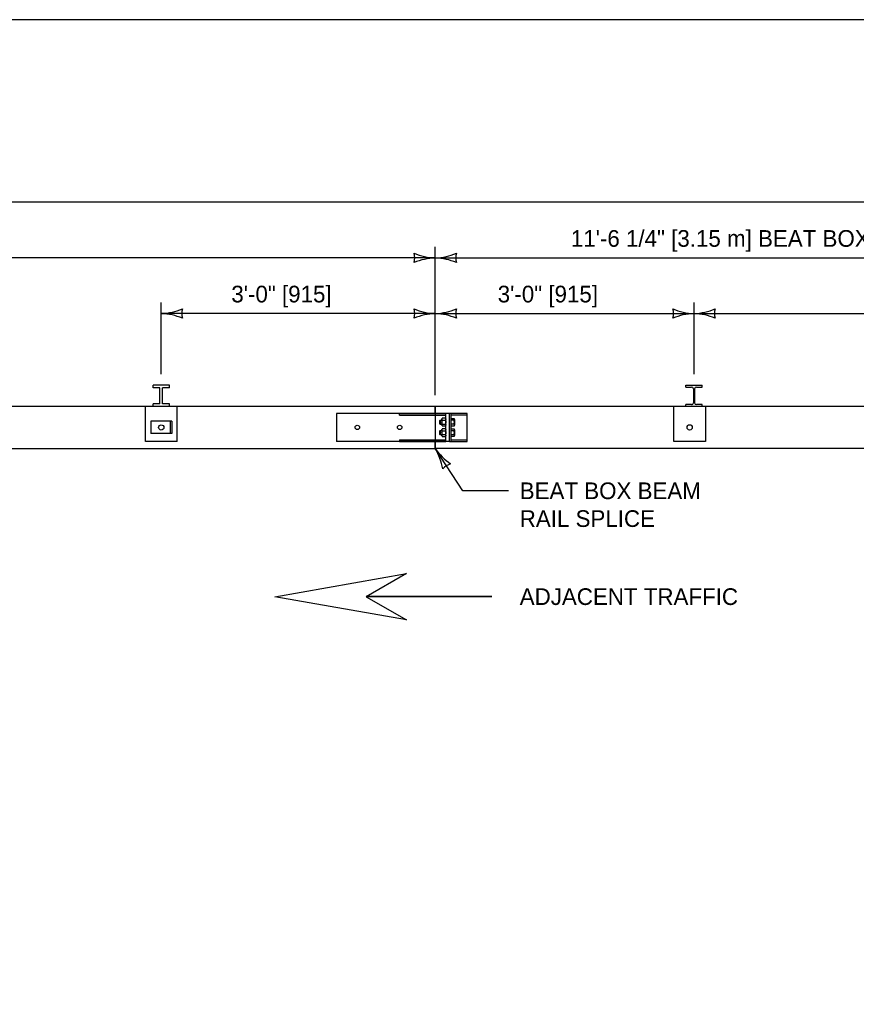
# Model space of a CAD drawing. Extents: x 49991.4 to 50021, y 49987.6 to 50011.4.
# Drawn here: x 50010.735 to 50013.742, y 49995.487 to 49998.999 of the extents above; entities that cross this region are included whole.
import ezdxf

# ---------------------------------------------------------------- set-up
doc = ezdxf.new("R2010")
doc.units = 0
for name, color, linetype in [('Level 1', 7, 'Continuous'), ('Level 2', 7, 'Continuous'), ('Level 3', 7, 'Continuous'), ('Level 4', 7, 'Continuous'), ('Level 63', 7, 'Continuous')]:
    doc.layers.add(name, color=color, linetype=linetype)

# ---------------------------------------------------------------- blocks, each defined once
blk = doc.blocks.new('HEX$NU')
at = {"layer": 'Level 63'}
for p, q in [((0, -0.32), (0, 0.32)), ((0.03, 0.43), (0.42, 0.43)), ((0.03, 0.22), (0.42, 0.22)), ((0.45, 0.32), (0.45, -0.32)), ((0.03, -0.22), (0.42, -0.22)), ((0.42, -0.43), (0.03, -0.43))]:
    blk.add_line(p, q, dxfattribs=at)
for centre, radius, start, end in [((0.21, 0.32), 0.21, 149.0201, 210.9799), ((0.8, 0), 0.796, 164.2217, 195.7782), ((0.24, 0.32), 0.21, 329.0201, 30.9799), ((-0.35, 0), 0.796, 344.2218, 15.7783), ((0.21, -0.32), 0.21, 149.0201, 210.9799), ((0.24, -0.32), 0.21, 329.0201, 30.9799)]:
    blk.add_arc(centre, radius, start, end, dxfattribs=at)

msp = doc.modelspace()

# ---------------------------------------------------------------- linework, layer by layer
at = {"layer": 'Level 1'}
for p, q in [((50011.2143, 49997.6755), (50011.2143, 49997.6847)), ((50011.2734, 49997.6847), (50011.2143, 49997.6847)), ((50011.2393, 49997.6755), (50011.2143, 49997.6755)), ((50011.2393, 49997.6179), (50011.2393, 49997.6755)), ((50011.2484, 49997.6179), (50011.2484, 49997.6755)), ((50011.2734, 49997.6755), (50011.2484, 49997.6755)), ((50011.2734, 49997.6755), (50011.2734, 49997.6847)), ((50013.1289, 49997.6846), (50013.1881, 49997.6846)), ((50013.1289, 49997.678), (50013.1289, 49997.6846)), ((50013.1289, 49997.678), (50013.15, 49997.678)), ((50013.1563, 49997.6717), (50013.1563, 49997.6216)), ((50013.1607, 49997.6717), (50013.1607, 49997.6216)), ((50013.167, 49997.678), (50013.1881, 49997.678)), ((50013.1881, 49997.678), (50013.1881, 49997.6846)), ((50012.2286, 49997.6087), (50006.713, 49997.6087)), ((50011.2393, 49997.6179), (50011.2143, 49997.6179)), ((50011.2143, 49997.6087), (50011.2143, 49997.6179)), ((50011.2734, 49997.6179), (50011.2484, 49997.6179)), ((50011.2734, 49997.6087), (50011.2734, 49997.6179)), ((50015.8846, 49997.6087), (50012.2286, 49997.6087)), ((50012.2286, 49997.5834), (50012.2286, 49997.6087)), ((50012.2286, 49997.6087), (50012.2286, 49997.5834)), ((50013.1998, 49997.6087), (50013.0855, 49997.6087)), ((50013.1289, 49997.6087), (50013.1289, 49997.6153)), ((50013.15, 49997.6153), (50013.1289, 49997.6153)), ((50013.1881, 49997.6087), (50013.1289, 49997.6087)), ((50013.1881, 49997.6153), (50013.167, 49997.6153)), ((50013.1881, 49997.6087), (50013.1881, 49997.6153)), ((50011.8732, 49997.5834), (50011.8732, 49997.4821)), ((50012.2794, 49997.5834), (50011.8732, 49997.5834)), ((50012.1001, 49997.5834), (50012.2667, 49997.5834)), ((50012.1001, 49997.577), (50012.1001, 49997.5834)), ((50012.1001, 49997.577), (50012.2667, 49997.577)), ((50012.2286, 49997.5834), (50012.2286, 49997.4821)), ((50012.2286, 49997.5834), (50012.2286, 49997.4821)), ((50012.2667, 49997.4821), (50012.2667, 49997.5834)), ((50012.2794, 49997.4821), (50012.2794, 49997.5834)), ((50012.2794, 49997.4821), (50012.2794, 49997.5834)), ((50012.3429, 49997.5834), (50012.2794, 49997.5834)), ((50012.2858, 49997.4821), (50012.2858, 49997.5834)), ((50012.3429, 49997.577), (50012.2858, 49997.577)), ((50012.3429, 49997.4821), (50012.3429, 49997.5834)), ((50011.206, 49997.555), (50011.206, 49997.5106)), ((50011.282, 49997.555), (50011.206, 49997.555)), ((50011.2756, 49997.555), (50011.2756, 49997.5106)), ((50011.282, 49997.555), (50011.282, 49997.5106)), ((50012.2461, 49997.5596), (50012.2445, 49997.558)), ((50012.2445, 49997.5454), (50012.2445, 49997.558)), ((50012.2461, 49997.5438), (50012.2445, 49997.5454)), ((50012.2461, 49997.5596), (50012.2461, 49997.5438)), ((50012.2461, 49997.5596), (50012.2525, 49997.5596)), ((50012.2525, 49997.558), (50012.2461, 49997.558)), ((50012.2461, 49997.5454), (50012.2525, 49997.5454)), ((50012.2525, 49997.5438), (50012.2461, 49997.5438)), ((50012.2962, 49997.5586), (50012.2858, 49997.5586)), ((50012.2962, 49997.5449), (50012.2858, 49997.5449)), ((50012.2973, 49997.562), (50012.2973, 49997.5414)), ((50011.282, 49997.5106), (50011.206, 49997.5106)), ((50012.2461, 49997.5217), (50012.2445, 49997.5201)), ((50012.2445, 49997.5074), (50012.2445, 49997.5201)), ((50012.2461, 49997.5058), (50012.2445, 49997.5074)), ((50012.2461, 49997.5217), (50012.2461, 49997.5058)), ((50012.2461, 49997.5217), (50012.2525, 49997.5217)), ((50012.2525, 49997.5201), (50012.2461, 49997.5201)), ((50012.2461, 49997.5074), (50012.2525, 49997.5074)), ((50012.2525, 49997.5058), (50012.2461, 49997.5058)), ((50012.2962, 49997.5206), (50012.2858, 49997.5206)), ((50012.2962, 49997.5069), (50012.2858, 49997.5069)), ((50012.2973, 49997.524), (50012.2973, 49997.5035)), ((50012.2794, 49997.4821), (50011.8732, 49997.4821)), ((50012.1001, 49997.4884), (50012.1001, 49997.4821)), ((50012.1001, 49997.4884), (50012.2667, 49997.4884)), ((50012.1001, 49997.4821), (50012.2667, 49997.4821)), ((50012.2286, 49997.4821), (50012.2286, 49997.4568)), ((50012.2286, 49997.4568), (50012.2286, 49997.4821)), ((50012.2794, 49997.4821), (50012.3429, 49997.4821)), ((50012.2858, 49997.4884), (50012.3429, 49997.4884)), ((50015.8846, 49997.4568), (50012.2286, 49997.4568)), ((50012.2286, 49997.4568), (50012.2286, 49997.4568)), ((50012.4322, 49996.9249), (50011.9803, 49996.9249)), ((50012.4322, 49996.9244), (50011.9803, 49996.9244))]:
    msp.add_line(p, q, dxfattribs=at)
for points in [[(49999.3835, 49998.9992), (50016.7501, 49998.9992), (50016.7501, 49987.7988), (49999.3835, 49987.7988)], [(50012.1248, 49996.8411), (50011.6519, 49996.9244), (50012.1248, 49997.0082), (50011.9805, 49996.9244)]]:
    msp.add_lwpolyline(points, close=True, dxfattribs=at)
for points in [[(50012.2962, 49997.538), (50012.2858, 49997.538), (50012.2858, 49997.5654), (50012.2962, 49997.5654)], [(50012.2962, 49997.5), (50012.2858, 49997.5), (50012.2858, 49997.5274), (50012.2962, 49997.5274)], [(50006.713, 49997.4568), (50012.2286, 49997.4568)]]:
    msp.add_lwpolyline(points, dxfattribs=at)
for centre in [(50011.244, 49997.5328), (50013.1429, 49997.5331)]:
    msp.add_circle(centre, 0.00948, dxfattribs=at)
for centre, major_axis, start_param, end_param in [((50013.15, 49997.6717), (-0.00635, 0), 3.141593, 4.712389), ((50013.167, 49997.6717), (-0.00635, 0), 4.712389, 6.283185), ((50013.15, 49997.6216), (-0.00635, 0), 1.570796, 3.141593), ((50013.167, 49997.6216), (-0.00635, 0), 0, 1.570796), ((50012.2914, 49997.562), (-0.00587, 0), 2.516161, 3.767024), ((50012.2755, 49997.5517), (-0.0218, 0), 2.821042, 3.462143), ((50012.2914, 49997.5414), (-0.00587, 0), 2.516163, 3.767023), ((50012.2914, 49997.524), (-0.00587, 0), 2.516161, 3.767024), ((50012.2755, 49997.5137), (-0.0218, 0), 2.821042, 3.462143), ((50012.2914, 49997.5035), (-0.00587, 0), 2.516163, 3.767023)]:
    msp.add_ellipse(centre, major_axis=major_axis, ratio=0.99715, start_param=start_param, end_param=end_param, dxfattribs=at)
for centre in [(50011.9485, 49997.5331), (50012.1008, 49997.5331)]:
    msp.add_ellipse(centre, major_axis=(-0.00793, 0), ratio=0.99715, dxfattribs=at)
at = {"layer": 'Level 3'}
for p, q in [((50015.7531, 49998.3423), (50001.2124, 49998.3423)), ((50012.2286, 49997.6487), (50012.2286, 49998.1823)), ((50012.2286, 49998.1423), (50001.2124, 49998.1423)), ((50012.2286, 49998.1423), (50015.7531, 49998.1423)), ((50011.2439, 49997.7247), (50011.2439, 49997.9823)), ((50013.1585, 49997.7246), (50013.1585, 49997.9823)), ((50012.2286, 49997.9423), (50011.2439, 49997.9423)), ((50012.2286, 49997.9423), (50013.1585, 49997.9423)), ((50013.1585, 49997.9423), (50015.7531, 49997.9423)), ((50012.328, 49997.3052), (50012.2286, 49997.4568)), ((50012.4922, 49997.3052), (50012.328, 49997.3052))]:
    msp.add_line(p, q, dxfattribs=at)
for centre, radius, start, end in [((50012.2378, 49998.3644), 0.2223, 247.456, 267.6395), ((50012.1004, 49998.1423), 0.0548, 342.1388, 17.8612), ((50012.2401, 49997.9096), 0.233, 92.8273, 112.0772), ((50012.2171, 49998.375), 0.233, 272.8273, 292.0772), ((50012.2195, 49997.9201), 0.2223, 67.456, 87.6395), ((50012.3568, 49998.1423), 0.0548, 162.1388, 197.8612), ((50011.2324, 49998.175), 0.233, 272.8273, 292.0772), ((50011.3721, 49997.9423), 0.0548, 162.1388, 197.8612), ((50012.2378, 49998.1644), 0.2223, 247.456, 267.6395), ((50012.1004, 49997.9423), 0.0548, 342.1388, 17.8612), ((50012.2171, 49998.175), 0.233, 272.8273, 292.0772), ((50012.3568, 49997.9423), 0.0548, 162.1388, 197.8612), ((50013.1677, 49998.1644), 0.2223, 247.456, 267.6395), ((50013.0303, 49997.9423), 0.0548, 342.1388, 17.8612), ((50013.147, 49998.175), 0.233, 272.8273, 292.0772), ((50013.2867, 49997.9423), 0.0548, 162.1388, 197.8612), ((50011.2347, 49997.7201), 0.2223, 67.456, 87.6395), ((50012.2401, 49997.7096), 0.233, 92.8273, 112.0772), ((50012.2195, 49997.7201), 0.2223, 67.456, 87.6395), ((50013.17, 49997.7096), 0.233, 92.8273, 112.0772), ((50013.1493, 49997.7201), 0.2223, 67.456, 87.6395), ((50012.0365, 49997.345), 0.2223, 10.0153, 30.1988), ((50012.4186, 49997.5917), 0.233, 215.3866, 234.6365), ((50012.2976, 49997.3487), 0.0548, 104.6981, 140.4205)]:
    msp.add_arc(centre, radius, start, end, dxfattribs=at)
at = {"layer": 'Level 4'}
for p, q in [((50011.1868, 49997.4821), (50011.1868, 49997.6087)), ((50011.3008, 49997.4821), (50011.3008, 49997.6087)), ((50013.0855, 49997.4821), (50013.0855, 49997.6087)), ((50013.1998, 49997.6087), (50013.1998, 49997.4821)), ((50011.3008, 49997.4821), (50011.1868, 49997.4821)), ((50013.1998, 49997.4821), (50013.0855, 49997.4821))]:
    msp.add_line(p, q, dxfattribs=at)

# ---------------------------------------------------------------- block references
at = {"layer": 'Level 1', "xscale": 0.031736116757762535, "yscale": -0.03164567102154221}
for p in [(50012.2526, 49997.5522), (50012.2526, 49997.5141)]:
    msp.add_blockref('HEX$NU', p, dxfattribs=at)

# ---------------------------------------------------------------- texts
at = {"layer": 'Level 2'}
for s, p in [('11\'-6 1/4" [3.15 m] BEAT BOX BEAM TERMINAL SECTION', (50012.7159, 49998.1823)), ('3\'-0" [915]', (50011.4957, 49997.9823)), ('3\'-0" [915]', (50012.453, 49997.9823)), ('BEAT BOX BEAM', (50012.5322, 49997.2752)), ('RAIL SPLICE', (50012.5322, 49997.1752)), ('ADJACENT TRAFFIC', (50012.5322, 49996.8947))]:
    msp.add_text(s, height=0.06, dxfattribs=at).set_placement(p)

doc.saveas('drawing.dxf')
